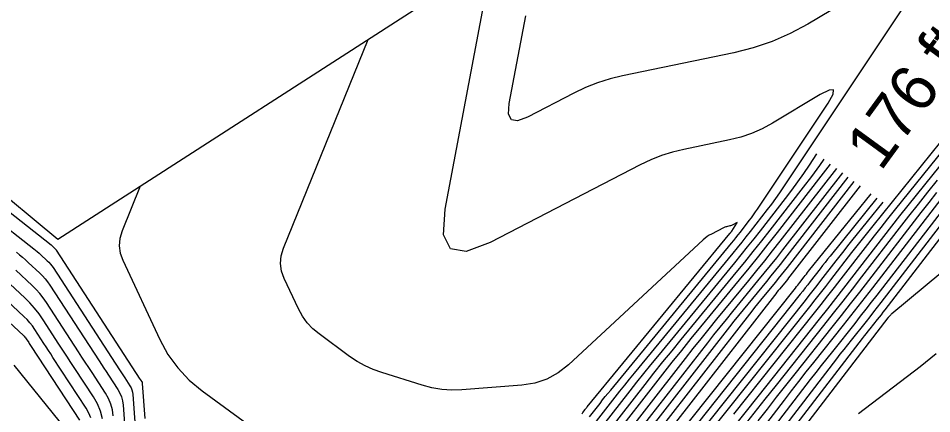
# Model space of a CAD drawing. Extents: x 7585033 to 7595090, y 547091 to 553471.
# Drawn here: x 7587336.2 to 7587459.7, y 548630.8 to 548684.2 of the extents above; entities that cross this region are included whole.
import ezdxf

# ---------------------------------------------------------------- set-up
doc = ezdxf.new("R2010")
doc.units = 0
for name, color, linetype in [('E_TERR_BNDRY_Perimeter', 7, 'Continuous'), ('E_TERR_DSPLAY_GeneralTx', 7, 'Continuous'), ('E_TERR_DSPLAY_MajContour', 7, 'Continuous'), ('E_TERR_DSPLAY_MinContour', 7, 'Continuous')]:
    doc.layers.add(name, color=color, linetype=linetype)

msp = doc.modelspace()

# ---------------------------------------------------------------- linework, layer by layer
at = {"layer": 'E_TERR_BNDRY_Perimeter'}
msp.add_lwpolyline([(7587396.27, 548689.6), (7587341.51, 548654.34), (7587331.58, 548662.53), (7587310.67, 548662.98), (7587309.19, 548661.65), (7587297.25, 548651.05), (7587291.31, 548643.22), (7587274.85, 548618.58), (7587263.08, 548595.27), (7587227.33, 548560.86)], dxfattribs=at)
at = {"layer": 'E_TERR_DSPLAY_MajContour'}
for points in [[(7587412.37, 548630.77), (7587412.44, 548630.86), (7587412.51, 548630.96), (7587412.8, 548631.33), (7587412.87, 548631.42), (7587412.95, 548631.52), (7587413.02, 548631.61), (7587413.1, 548631.7), (7587432.39, 548655.14), (7587432.41, 548655.16), (7587432.43, 548655.19), (7587432.45, 548655.22), (7587432.47, 548655.25), (7587432.56, 548655.36), (7587432.58, 548655.38), (7587432.6, 548655.41), (7587432.62, 548655.44), (7587432.64, 548655.47), (7587433.33, 548656.51), (7587433.38, 548656.59), (7587433.38, 548656.63), (7587433.34, 548656.63), (7587433.25, 548656.59), (7587432.79, 548656.31), (7587432.69, 548656.25), (7587432.58, 548656.21), (7587432.48, 548656.17), (7587432.37, 548656.15), (7587431.92, 548656.05), (7587431.81, 548656.03), (7587431.7, 548655.99), (7587431.6, 548655.95), (7587431.5, 548655.9), (7587429.88, 548655.06), (7587429.58, 548654.9), (7587429.3, 548654.71), (7587429.03, 548654.51), (7587428.77, 548654.28), (7587410.54, 548637.37), (7587409.15, 548636.28), (7587407.64, 548635.45), (7587406.01, 548634.9), (7587404.26, 548634.63), (7587396.13, 548634.01), (7587394.77, 548633.97), (7587393.43, 548634.06), (7587392.1, 548634.27), (7587390.79, 548634.62), (7587385.32, 548636.33), (7587384.16, 548636.74), (7587383.05, 548637.24), (7587381.99, 548637.83), (7587380.97, 548638.52), (7587376.83, 548641.55), (7587375.97, 548642.26), (7587375.22, 548643.06), (7587374.58, 548643.95), (7587374.05, 548644.93), (7587372.13, 548649.03), (7587371.77, 548650.05), (7587371.63, 548651.09), (7587371.72, 548652.12), (7587372.03, 548653.17), (7587383.49, 548681.37)], [(7587445.08, 548665.16), (7587444.5, 548664.34), (7587443.41, 548662.85), (7587442.29, 548661.39), (7587437.78, 548655.58), (7587436.64, 548654.13), (7587435.5, 548652.69), (7587434.34, 548651.26), (7587433.18, 548649.84), (7587425.75, 548640.8), (7587424.51, 548639.29), (7587423.28, 548637.77), (7587422.07, 548636.24), (7587420.86, 548634.71), (7587415.91, 548628.35)], [(7587467.34, 548664.69), (7587452.78, 548645.81), (7587452.28, 548645.17), (7587451.78, 548644.53), (7587451.28, 548643.89), (7587450.78, 548643.26), (7587448.76, 548640.73), (7587448.26, 548640.09), (7587447.76, 548639.46), (7587447.26, 548638.82), (7587446.77, 548638.18), (7587419.37, 548602.51)], [(7587415.82, 548621.28), (7587432.36, 548642.5), (7587432.97, 548643.28), (7587433.59, 548644.05), (7587434.21, 548644.82), (7587434.84, 548645.59), (7587437.35, 548648.64), (7587437.98, 548649.4), (7587438.6, 548650.17), (7587439.21, 548650.95), (7587439.82, 548651.73), (7587448.39, 548662.75)], [(7587434.19, 548628.94), (7587435.67, 548630.85), (7587437.16, 548632.75), (7587438.66, 548634.64), (7587445.1, 548642.72), (7587446.4, 548644.35), (7587447.68, 548645.98), (7587448.96, 548647.62), (7587450.23, 548649.26), (7587455.3, 548655.84), (7587456.57, 548657.48), (7587457.86, 548659.11), (7587459.15, 548660.74), (7587460.45, 548662.36)], [(7587453.04, 548659.36), (7587448.83, 548654.14), (7587448.3, 548653.47), (7587447.77, 548652.8), (7587447.24, 548652.13), (7587446.72, 548651.46), (7587444.64, 548648.76), (7587444.12, 548648.09), (7587443.59, 548647.42), (7587443.07, 548646.75), (7587442.54, 548646.08), (7587425.41, 548624.6)], [(7587332.51, 548657.57), (7587338.27, 548653.07), (7587338.5, 548652.88), (7587338.74, 548652.69), (7587338.97, 548652.49), (7587339.19, 548652.28), (7587340.09, 548651.45), (7587340.31, 548651.24), (7587340.51, 548651.01), (7587340.7, 548650.77), (7587340.87, 548650.52), (7587349.87, 548636.69), (7587350.05, 548636.42), (7587350.22, 548636.15), (7587350.39, 548635.89), (7587350.57, 548635.62), (7587351.26, 548634.56), (7587351.42, 548634.29), (7587351.53, 548634), (7587351.61, 548633.7), (7587351.66, 548633.39), (7587352.97, 548615.37)], [(7587345.98, 548630.2), (7587345.71, 548630.87), (7587345.35, 548631.51), (7587340.86, 548638.39), (7587340.55, 548638.86), (7587340.24, 548639.33), (7587339.93, 548639.81), (7587339.62, 548640.28), (7587338.39, 548642.18), (7587338.07, 548642.64), (7587337.72, 548643.08), (7587337.35, 548643.5), (7587336.94, 548643.89), (7587331.36, 548649.08)]]:
    msp.add_lwpolyline(points, dxfattribs=at)
at = {"layer": 'E_TERR_DSPLAY_MinContour'}
for points in [[(7587459.36, 548691.1), (7587439.62, 548661.42), (7587439.09, 548660.64), (7587438.55, 548659.87), (7587438, 548659.12), (7587437.43, 548658.37), (7587435.13, 548655.41), (7587434.55, 548654.68), (7587433.97, 548653.94), (7587433.38, 548653.21), (7587432.78, 548652.49), (7587419.42, 548636.25), (7587418.77, 548635.45), (7587418.12, 548634.64), (7587417.47, 548633.83), (7587416.83, 548633.02), (7587414.28, 548629.75)], [(7587452.23, 548689.02), (7587442.91, 548683.44), (7587440.53, 548682.15), (7587438.08, 548681.07), (7587435.54, 548680.21), (7587432.92, 548679.55), (7587417.87, 548676.44), (7587416.17, 548676.02), (7587414.5, 548675.49), (7587412.87, 548674.85), (7587411.28, 548674.1), (7587405.01, 548670.85), (7587403.68, 548670.35), (7587402.83, 548670.5), (7587402.44, 548671.28), (7587402.53, 548672.69), (7587404.77, 548684.56)], [(7587413.4, 548630.35), (7587414.82, 548632.17), (7587415.17, 548632.63), (7587415.53, 548633.08), (7587415.89, 548633.53), (7587416.26, 548633.98), (7587432.59, 548653.81), (7587432.89, 548654.19), (7587433.2, 548654.57), (7587433.5, 548654.95), (7587433.8, 548655.33), (7587434.99, 548656.87), (7587435.29, 548657.25), (7587435.58, 548657.64), (7587435.86, 548658.04), (7587436.13, 548658.44), (7587445.66, 548672.77), (7587446.33, 548673.95), (7587446.37, 548674.53), (7587445.79, 548674.52), (7587444.57, 548673.9), (7587438.12, 548670.04), (7587436.75, 548669.29), (7587435.32, 548668.67), (7587433.85, 548668.16), (7587432.33, 548667.78), (7587426.15, 548666.5), (7587424.62, 548666.13), (7587423.13, 548665.66), (7587421.67, 548665.09), (7587420.26, 548664.41), (7587399.97, 548653.9), (7587396.7, 548652.69), (7587394.6, 548653.04), (7587393.66, 548654.95), (7587393.88, 548658.43), (7587399.38, 548687.58)], [(7587429.16, 548627.66), (7587443.18, 548645.24), (7587443.9, 548646.15), (7587444.62, 548647.06), (7587445.33, 548647.97), (7587446.04, 548648.89), (7587448.86, 548652.55), (7587449.57, 548653.47), (7587450.29, 548654.38), (7587451.01, 548655.29), (7587451.73, 548656.19), (7587466.11, 548674.02)], [(7587432.91, 548630.71), (7587443.82, 548644.4), (7587444.73, 548645.55), (7587445.64, 548646.7), (7587446.54, 548647.85), (7587447.43, 548649.01), (7587451.01, 548653.65), (7587451.91, 548654.81), (7587452.81, 548655.96), (7587453.72, 548657.11), (7587454.64, 548658.25), (7587466.16, 548672.53)], [(7587466.21, 548671.05), (7587457.54, 548660.3), (7587456.43, 548658.92), (7587455.33, 548657.54), (7587454.24, 548656.14), (7587453.16, 548654.74), (7587448.83, 548649.13), (7587447.75, 548647.73), (7587446.66, 548646.34), (7587445.56, 548644.95), (7587444.46, 548643.56), (7587436.14, 548633.12), (7587434.39, 548630.91), (7587432.65, 548628.7)], [(7587470.38, 548666.94), (7587453.31, 548644.81), (7587453.06, 548644.49), (7587452.81, 548644.16), (7587452.56, 548643.84), (7587452.3, 548643.52), (7587451.29, 548642.25), (7587451.03, 548641.93), (7587450.78, 548641.61), (7587450.53, 548641.29), (7587450.28, 548640.96), (7587419.14, 548600.42)], [(7587444.09, 548665.88), (7587443.1, 548664.39), (7587442.32, 548663.24), (7587441.52, 548662.11), (7587440.7, 548660.99), (7587439.86, 548659.88), (7587436.45, 548655.5), (7587435.6, 548654.4), (7587434.73, 548653.32), (7587433.86, 548652.24), (7587432.98, 548651.16), (7587422.58, 548638.53), (7587421.64, 548637.37), (7587420.7, 548636.21), (7587419.77, 548635.04), (7587418.85, 548633.86), (7587415.17, 548629.15)], [(7587446.78, 548663.92), (7587439.15, 548654.1), (7587438.1, 548652.77), (7587437.04, 548651.44), (7587435.98, 548650.11), (7587434.9, 548648.8), (7587430.58, 548643.55), (7587429.51, 548642.23), (7587428.44, 548640.91), (7587427.38, 548639.58), (7587426.33, 548638.24), (7587415.87, 548624.82)], [(7587415.89, 548626.58), (7587423.32, 548636.11), (7587424.58, 548637.73), (7587425.86, 548639.34), (7587427.15, 548640.94), (7587428.45, 548642.53), (7587433.68, 548648.88), (7587434.98, 548650.47), (7587436.27, 548652.07), (7587437.55, 548653.68), (7587438.81, 548655.29), (7587444.73, 548662.9), (7587445.96, 548664.52)], [(7587447.58, 548663.33), (7587439.48, 548652.92), (7587438.66, 548651.86), (7587437.82, 548650.81), (7587436.98, 548649.76), (7587436.13, 548648.72), (7587432.71, 548644.57), (7587431.86, 548643.53), (7587431.01, 548642.48), (7587430.18, 548641.43), (7587429.35, 548640.37), (7587415.84, 548623.05)], [(7587464.3, 548662.45), (7587452.24, 548646.8), (7587451.5, 548645.85), (7587450.76, 548644.89), (7587450.01, 548643.94), (7587449.26, 548642.99), (7587446.24, 548639.2), (7587445.48, 548638.26), (7587444.74, 548637.3), (7587443.99, 548636.35), (7587443.25, 548635.39), (7587419.6, 548604.59)], [(7587352.65, 548661.51), (7587350.2, 548655.48), (7587349.9, 548654.48), (7587349.82, 548653.48), (7587349.95, 548652.49), (7587350.3, 548651.51), (7587355.3, 548640.82), (7587356.4, 548638.8), (7587357.72, 548636.96), (7587359.26, 548635.31), (7587361.03, 548633.85), (7587369.57, 548627.6)], [(7587450, 548661.58), (7587440.49, 548649.35), (7587440.32, 548649.13), (7587440.15, 548648.91), (7587439.97, 548648.7), (7587439.8, 548648.48), (7587439.09, 548647.62), (7587438.92, 548647.41), (7587438.74, 548647.19), (7587438.57, 548646.98), (7587438.4, 548646.76), (7587415.78, 548617.74)], [(7587415.8, 548619.51), (7587435.38, 548644.63), (7587435.77, 548645.13), (7587436.17, 548645.62), (7587436.56, 548646.11), (7587436.96, 548646.6), (7587438.57, 548648.56), (7587438.97, 548649.05), (7587439.37, 548649.54), (7587439.76, 548650.04), (7587440.15, 548650.54), (7587449.19, 548662.16)], [(7587417.92, 548618.48), (7587441.25, 548647.76), (7587441.4, 548647.95), (7587441.55, 548648.14), (7587441.7, 548648.33), (7587441.84, 548648.52), (7587442.43, 548649.27), (7587442.57, 548649.46), (7587442.72, 548649.65), (7587442.87, 548649.84), (7587443.02, 548650.02), (7587451.47, 548660.5)], [(7587419.82, 548606.67), (7587439.74, 548632.6), (7587440.72, 548633.88), (7587441.71, 548635.15), (7587442.71, 548636.42), (7587443.71, 548637.68), (7587447.73, 548642.73), (7587448.73, 548643.99), (7587449.73, 548645.25), (7587450.72, 548646.53), (7587451.71, 548647.8), (7587461.27, 548660.2)], [(7587452.26, 548659.93), (7587445.92, 548652.08), (7587445.58, 548651.65), (7587445.24, 548651.23), (7587444.91, 548650.8), (7587444.57, 548650.37), (7587443.24, 548648.64), (7587442.91, 548648.21), (7587442.57, 548647.78), (7587442.23, 548647.35), (7587441.9, 548646.92), (7587421.67, 548621.54)], [(7587436.22, 548629.82), (7587437.45, 548631.41), (7587438.69, 548633), (7587439.94, 548634.58), (7587441.19, 548636.16), (7587446.21, 548642.46), (7587447.46, 548644.04), (7587448.7, 548645.62), (7587449.94, 548647.2), (7587451.18, 548648.8), (7587458.23, 548657.95), (7587459.3, 548659.32), (7587460.37, 548660.69)], [(7587353.32, 548630.15), (7587352.98, 548634.85), (7587352.97, 548634.91), (7587352.96, 548634.96), (7587352.94, 548635.02), (7587352.91, 548635.07), (7587352.78, 548635.26), (7587352.75, 548635.31), (7587352.72, 548635.36), (7587352.68, 548635.41), (7587352.65, 548635.46), (7587341.32, 548652.88), (7587341.27, 548652.94), (7587341.22, 548653.01), (7587341.17, 548653.06), (7587341.11, 548653.12), (7587340.87, 548653.34), (7587340.81, 548653.4), (7587340.75, 548653.45), (7587340.69, 548653.5), (7587340.63, 548653.55), (7587333.33, 548659.26)], [(7587335.91, 548652.59), (7587336.32, 548652.26), (7587336.73, 548651.92), (7587337.12, 548651.58), (7587337.52, 548651.22), (7587339.07, 548649.78), (7587339.45, 548649.41), (7587339.8, 548649.01), (7587340.12, 548648.6), (7587340.42, 548648.17), (7587347.1, 548637.92), (7587347.41, 548637.43), (7587347.73, 548636.95), (7587348.04, 548636.47), (7587348.36, 548635.98), (7587349.62, 548634.05), (7587349.9, 548633.56), (7587350.11, 548633.04), (7587350.25, 548632.5), (7587350.33, 548631.94), (7587351.33, 548618.19)], [(7587418.92, 548598.34), (7587453.79, 548643.75), (7587453.81, 548643.77), (7587453.83, 548643.8), (7587453.84, 548643.81), (7587454.08, 548644.11), (7587454.12, 548644.16), (7587454.16, 548644.21), (7587454.21, 548644.26), (7587454.26, 548644.3), (7587465.42, 548653.56)], [(7587349.01, 548630.48), (7587348.9, 548631.3), (7587348.69, 548632.08), (7587348.38, 548632.83), (7587347.97, 548633.55), (7587346.14, 548636.34), (7587345.69, 548637.04), (7587345.23, 548637.74), (7587344.77, 548638.44), (7587344.32, 548639.14), (7587339.98, 548645.81), (7587339.55, 548646.43), (7587339.08, 548647.02), (7587338.58, 548647.58), (7587338.05, 548648.11), (7587335.84, 548650.16)], [(7587347.54, 548630.09), (7587347.26, 548631.12), (7587346.86, 548632.1), (7587346.33, 548633.04), (7587343.81, 548636.9), (7587343.27, 548637.72), (7587342.74, 548638.54), (7587342.2, 548639.36), (7587341.67, 548640.18), (7587339.53, 548643.46), (7587338.97, 548644.26), (7587338.37, 548645.02), (7587337.72, 548645.75), (7587337.03, 548646.43), (7587333.69, 548649.53)], [(7587329.03, 548648.62), (7587336.86, 548641.35), (7587336.97, 548641.25), (7587337.07, 548641.13), (7587337.16, 548641.01), (7587337.25, 548640.89), (7587337.58, 548640.38), (7587337.66, 548640.25), (7587337.74, 548640.13), (7587337.83, 548640), (7587337.91, 548639.87), (7587344.43, 548629.89)], [(7587460.28, 548638.86), (7587459.56, 548638.27), (7587458.83, 548637.7), (7587458.09, 548637.13), (7587449.77, 548630.76)], [(7587335.58, 548637.34), (7587342.58, 548628.66), (7587342.64, 548628.57), (7587342.7, 548628.48), (7587342.75, 548628.39), (7587342.79, 548628.29), (7587342.94, 548627.89), (7587342.97, 548627.79), (7587342.99, 548627.68), (7587342.99, 548627.58), (7587342.97, 548627.48), (7587340.87, 548617.23), (7587340.59, 548616.08), (7587340.23, 548614.96), (7587339.78, 548613.88), (7587339.24, 548612.82), (7587336.26, 548607.44), (7587336.03, 548607.01)]]:
    msp.add_lwpolyline(points, dxfattribs=at)

# ---------------------------------------------------------------- texts
at = {"layer": 'E_TERR_DSPLAY_GeneralTx'}
msp.add_text('176 ft', height=6.3, rotation=53.9491, dxfattribs=at).set_placement((7587452.77, 548663.41))

doc.saveas('drawing.dxf')
